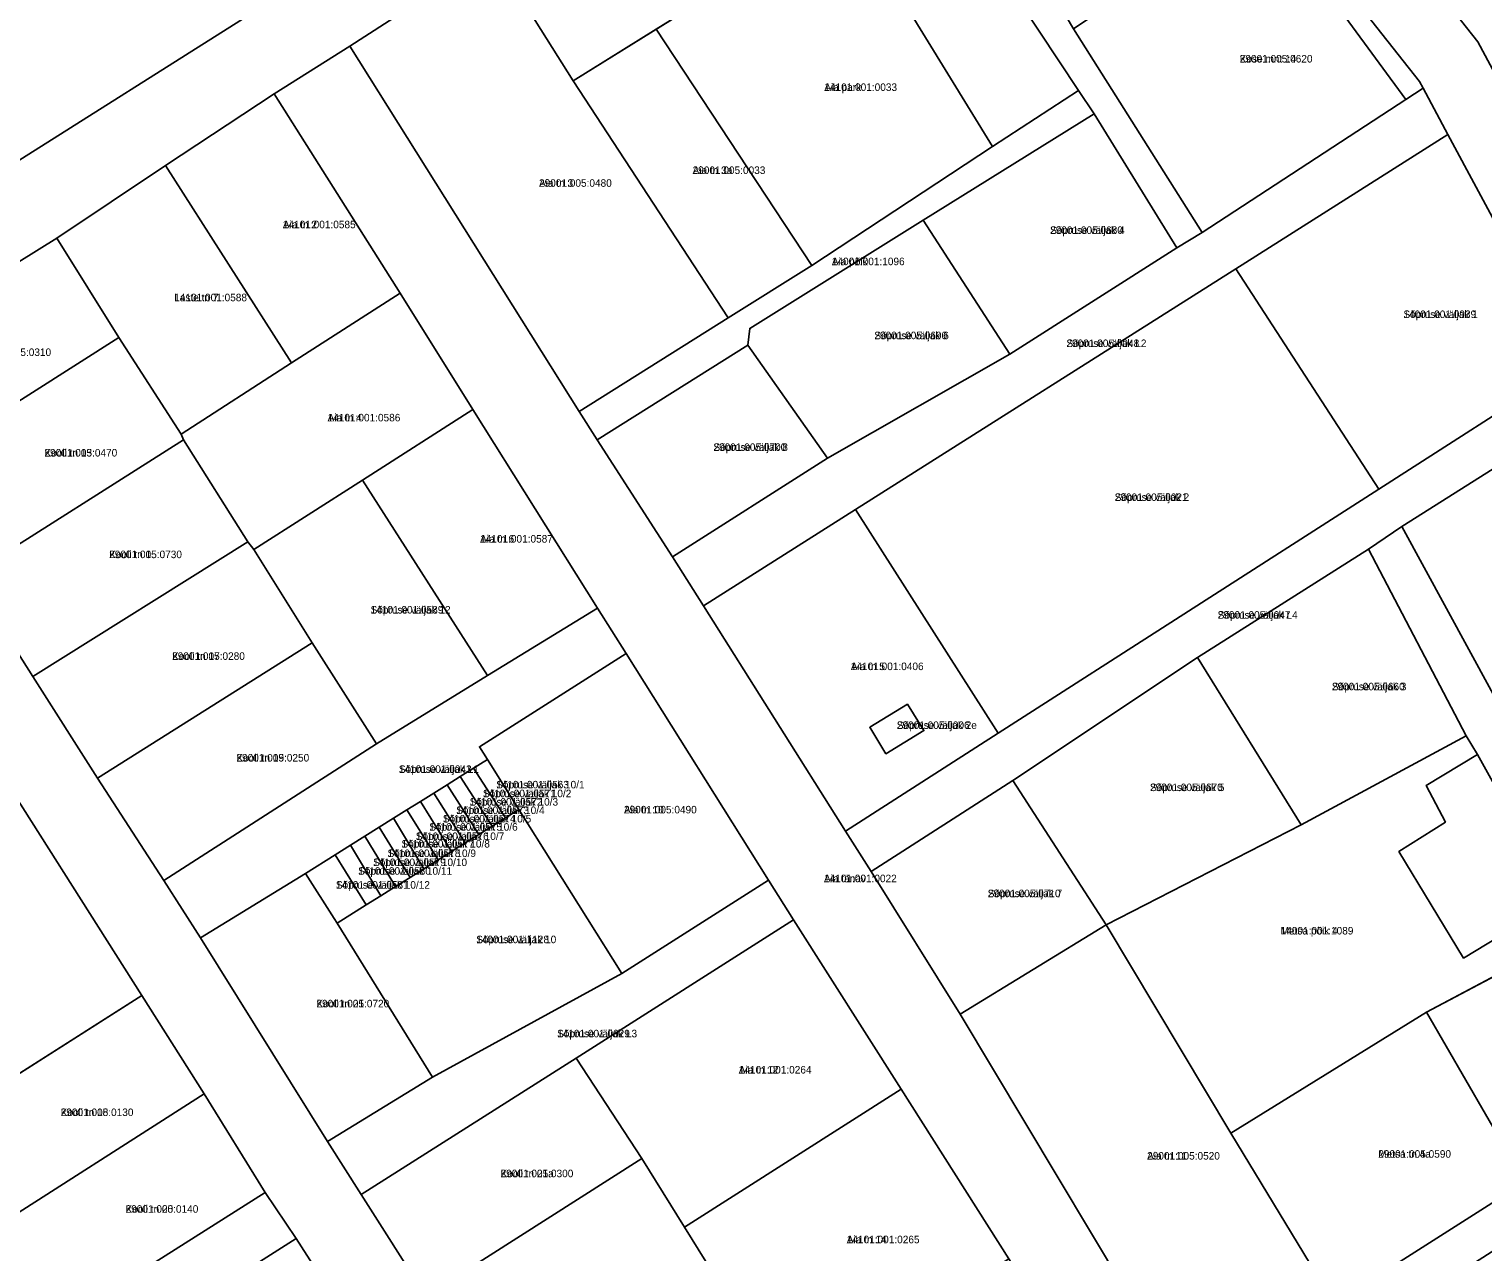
# Model space of a CAD drawing. Extents: x 566437 to 602312, y 6556921 to 6586574.
# Drawn here: x 575929.9 to 576219.6, y 6577437.6 to 6577681.1 of the extents above; entities that cross this region are included whole.
import ezdxf

# ---------------------------------------------------------------- set-up
doc = ezdxf.new("R2010")
doc.units = 0
for name, color, linetype in [('L_AADRESS', 7, 'Continuous'), ('PIIR', 7, 'Continuous'), ('TUNNUS', 7, 'Continuous')]:
    doc.layers.add(name, color=color, linetype=linetype)

msp = doc.modelspace()

# ---------------------------------------------------------------- linework, layer by layer
at = {"layer": 'PIIR'}
for points in [[(575658.06, 6577871.3), (575761.81, 6577796.47), (575774.21, 6577790.58), (575786.23, 6577773.43), (575799.52, 6577754.47), (575821.05, 6577726.98), (575839.49, 6577696.73), (575849.92, 6577679.85), (575860.57, 6577663.11), (575871.28, 6577646.07), (575883.63, 6577626.98), (575892.42, 6577612.75), (575905.11, 6577592.51), (575917.95, 6577572.24), (575930.64, 6577552.15), (575943.56, 6577531.93), (575956.74, 6577511.55), (575964.05, 6577500.13), (575989.38, 6577459.52), (575996.11, 6577448.97), (576008.97, 6577428.71)], [(575991.44, 6577860.93), (576095.59, 6577805.76), (576121.84, 6577790.98), (576139.55, 6577776.01), (576151.7, 6577763.24), (576218.61, 6577678.56), (576248.16, 6577623.5), (576275.63, 6577565.39), (576304.7, 6577497.45), (576310.07, 6577477.46), (576311.83, 6577470.8), (576312.75, 6577468.55), (576342.78, 6577388.3)], [(575996.15, 6577419.93), (575983.17, 6577440.22), (575976.96, 6577449.41), (575964.78, 6577469.07), (575952.38, 6577488.6), (575920, 6577539.6), (575917.74, 6577546.52), (575791.8, 6577745.05), (575785.06, 6577754.7), (575770.14, 6577776.75), (575727.61, 6577807.92), (575657.86, 6577856.39)], [(576320.8, 6577407.04), (576299.03, 6577465.13), (576295.24, 6577478.98), (576291.81, 6577491.53), (576291.47, 6577492.76), (576262.84, 6577559.68), (576241.04, 6577605.81), (576237.16, 6577614.03), (576235.63, 6577617.27), (576212.64, 6577660.14), (576207.7, 6577669.35), (576206.98, 6577670.69), (576141.22, 6577753.94), (576128.2, 6577767.59), (576127.04, 6577768.85), (576113.97, 6577779.34), (576111.82, 6577780.55), (576088.98, 6577793.42), (576036.81, 6577819.97), (575971.27, 6577855.43)], [(576248.16, 6577623.5), (576218.61, 6577678.56), (576151.7, 6577763.24), (576139.55, 6577776.01), (576157.74, 6577790.18), (576177.37, 6577805.48), (576182.51, 6577802.45), (576199.32, 6577795.07), (576218.92, 6577789.93), (576233.6, 6577787.54)]]:
    msp.add_lwpolyline(points, dxfattribs=at)
for points in [[(575892.66, 6577706.65), (575884.17, 6577719.47), (575919.58, 6577743.64), (575973.08, 6577774.74), (575982.13, 6577780.1), (576000.38, 6577791.22), (576049.23, 6577769.36), (576039.79, 6577762.97), (576056.89, 6577736.43), (576020.27, 6577713.34), (575926.11, 6577653.83), (575913.93, 6577673.08), (575903.24, 6577689.92)], [(575957.12, 6577653.94), (575935.45, 6577639.5), (575892.42, 6577612.75), (575883.63, 6577626.98), (575926.11, 6577653.83), (576020.27, 6577713.34), (576056.89, 6577736.43), (576074.81, 6577747.63), (576094.84, 6577760.23), (576106.96, 6577774.73), (576111.82, 6577780.55), (576113.97, 6577779.34), (576127.04, 6577768.85), (576128.2, 6577767.59), (576126.36, 6577766.11), (576099.04, 6577744.42), (576093.35, 6577740.83), (576057.79, 6577718.18), (576022.41, 6577696.17), (575993.83, 6577677.75), (575978.79, 6577668.22)], [(576207.7, 6577669.35), (576204.26, 6577667.11), (576175.5, 6577706.32), (576153.23, 6577735.81), (576126.36, 6577766.11), (576128.2, 6577767.59), (576141.22, 6577753.94), (576206.98, 6577670.69)], [(576093.35, 6577740.83), (576099.04, 6577744.42), (576118.48, 6577714.05), (576138.05, 6577681.15), (576163.66, 6577640.63), (576158.59, 6577637.57), (576142.12, 6577664.25), (576139.02, 6577668.9), (576111.36, 6577710.69), (576108.67, 6577714.61)], [(576057.79, 6577718.18), (576072.98, 6577692.38), (576038.36, 6577670.81), (576022.41, 6577696.17)], [(576121.88, 6577657.71), (576085.9, 6577634.01), (576054.86, 6577681.09), (576072.98, 6577692.38), (576108.67, 6577714.61), (576111.36, 6577710.69), (576095.69, 6577700.37)], [(576139.02, 6577668.9), (576121.88, 6577657.71), (576095.69, 6577700.37), (576111.36, 6577710.69)], [(576204.26, 6577667.11), (576163.66, 6577640.63), (576138.05, 6577681.15), (576175.5, 6577706.32)], [(576022.41, 6577696.17), (576038.36, 6577670.81), (576069.23, 6577623.6), (576039.56, 6577604.97), (575993.83, 6577677.75)], [(576038.36, 6577670.81), (576054.86, 6577681.09), (576085.9, 6577634.01), (576069.23, 6577623.6)], [(576115.45, 6577484.94), (576160.97, 6577408.98), (576166.46, 6577400.22), (576168.72, 6577396.61), (576197.83, 6577350.25), (576184.67, 6577342.16), (576172.06, 6577362.16), (576146.63, 6577402.38), (576125.16, 6577436.16), (576103.72, 6577469.96), (576082.23, 6577503.72), (576077.25, 6577511.63), (576048.87, 6577556.78), (576043.18, 6577565.81), (576018.33, 6577605.34), (576003.86, 6577628.49), (575978.79, 6577668.22), (575993.83, 6577677.75), (576039.56, 6577604.97), (576043.13, 6577599.29), (576058.11, 6577576.02), (576064.29, 6577566.24), (576092.62, 6577521.38), (576097.71, 6577513.32)], [(575982.22, 6577614.66), (575957.12, 6577653.94), (575978.79, 6577668.22), (576003.86, 6577628.49)], [(576073.17, 6577618.17), (576043.13, 6577599.29), (576039.56, 6577604.97), (576069.23, 6577623.6), (576085.9, 6577634.01), (576121.88, 6577657.71), (576139.02, 6577668.9), (576142.12, 6577664.25), (576108.09, 6577643.04), (576073.52, 6577621.5)], [(576058.11, 6577576.02), (576089.04, 6577595.66), (576125.31, 6577616.4), (576158.59, 6577637.57), (576163.66, 6577640.63), (576204.26, 6577667.11), (576207.7, 6577669.35), (576212.64, 6577660.14), (576170.37, 6577633.39), (576094.62, 6577585.44), (576064.29, 6577566.24)], [(576158.59, 6577637.57), (576125.31, 6577616.4), (576108.09, 6577643.04), (576142.12, 6577664.25)], [(576237.16, 6577614.03), (576198.88, 6577589.49), (576170.37, 6577633.39), (576212.64, 6577660.14), (576235.63, 6577617.27)], [(575947.82, 6577619.72), (575935.45, 6577639.5), (575957.12, 6577653.94), (575982.22, 6577614.66), (575960.21, 6577600.43)], [(576125.31, 6577616.4), (576089.04, 6577595.66), (576073.17, 6577618.17), (576073.52, 6577621.5), (576108.09, 6577643.04)], [(575935.45, 6577639.5), (575947.82, 6577619.72), (575905.11, 6577592.51), (575892.42, 6577612.75)], [(576094.62, 6577585.44), (576170.37, 6577633.39), (576198.88, 6577589.49), (576123.04, 6577540.88)], [(575960.7, 6577599.32), (575960.21, 6577600.43), (575982.22, 6577614.66), (576003.86, 6577628.49), (576018.33, 6577605.34), (575996.39, 6577591.3), (575974.69, 6577577.47), (575973.53, 6577579.02)], [(575917.95, 6577572.24), (575905.11, 6577592.51), (575947.82, 6577619.72), (575960.21, 6577600.43), (575960.7, 6577599.32)], [(576089.04, 6577595.66), (576058.11, 6577576.02), (576043.13, 6577599.29), (576073.17, 6577618.17)], [(576092.62, 6577521.38), (576123.04, 6577540.88), (576198.88, 6577589.49), (576237.16, 6577614.03), (576241.04, 6577605.81), (576236.78, 6577603.12), (576203.47, 6577582.07), (576196.78, 6577577.52), (576162.75, 6577555.97), (576125.94, 6577531.47), (576097.71, 6577513.32)], [(576021.26, 6577552.35), (575996.39, 6577591.3), (576018.33, 6577605.34), (576043.18, 6577565.81)], [(576258.53, 6577557.41), (576225.68, 6577541.19), (576203.47, 6577582.07), (576236.78, 6577603.12)], [(575960.7, 6577599.32), (575973.53, 6577579.02), (575930.64, 6577552.15), (575917.95, 6577572.24)], [(575986.33, 6577558.9), (575974.69, 6577577.47), (575996.39, 6577591.3), (576021.26, 6577552.35), (575999.17, 6577538.73)], [(576094.62, 6577585.44), (576123.04, 6577540.88), (576092.62, 6577521.38), (576064.29, 6577566.24)], [(576196.78, 6577577.52), (576203.47, 6577582.07), (576225.68, 6577541.19), (576241.47, 6577510.81), (576261.64, 6577473), (576256.47, 6577469.75), (576238.26, 6577501.09), (576218.5, 6577536.6), (576216.28, 6577540.36)], [(575973.53, 6577579.02), (575974.69, 6577577.47), (575986.33, 6577558.9), (575943.56, 6577531.93), (575930.64, 6577552.15)], [(576216.28, 6577540.36), (576183.39, 6577522.62), (576162.75, 6577555.97), (576196.78, 6577577.52)], [(576021.26, 6577535.63), (576018.47, 6577533.88), (576015.85, 6577532.24), (576013.2, 6577530.59), (576010.54, 6577528.93), (576007.9, 6577527.27), (576005.21, 6577525.59), (576002.54, 6577523.92), (575999.68, 6577522.13), (575996.85, 6577520.36), (575993.95, 6577518.55), (575990.92, 6577516.65), (575985, 6577512.95), (575964.05, 6577500.13), (575956.74, 6577511.55), (575999.17, 6577538.73), (576021.26, 6577552.35), (576043.18, 6577565.81), (576048.87, 6577556.78), (576019.67, 6577538.17)], [(575986.33, 6577558.9), (575999.17, 6577538.73), (575956.74, 6577511.55), (575943.56, 6577531.93)], [(576077.25, 6577511.63), (576048.06, 6577493.02), (576027.51, 6577525.69), (576021.26, 6577535.63), (576019.67, 6577538.17), (576048.87, 6577556.78)], [(576183.39, 6577522.62), (576144.55, 6577502.72), (576125.94, 6577531.47), (576162.75, 6577555.97)], [(576104.92, 6577546.65), (576108.21, 6577541.41), (576100.66, 6577536.79), (576097.43, 6577542.07)], [(576097.43, 6577542.07), (576100.66, 6577536.79), (576108.21, 6577541.41), (576104.92, 6577546.65)], [(575851.95, 6577497.56), (575920, 6577539.6), (575952.38, 6577488.6), (575916.78, 6577465.99), (575904.32, 6577486.07), (575870.5, 6577465.08)], [(576208.36, 6577485.34), (576169.39, 6577461.19), (576144.55, 6577502.72), (576183.39, 6577522.62), (576216.28, 6577540.36), (576218.5, 6577536.6), (576208.28, 6577530.44), (576212.12, 6577523.18), (576202.87, 6577517.29), (576215.74, 6577496.07), (576225.14, 6577501.77), (576228.78, 6577496.1)], [(576018.47, 6577533.88), (576021.26, 6577535.63), (576027.51, 6577525.69), (576024.84, 6577524.02)], [(576218.5, 6577536.6), (576238.26, 6577501.09), (576228.78, 6577496.1), (576225.14, 6577501.77), (576215.74, 6577496.07), (576202.87, 6577517.29), (576212.12, 6577523.18), (576208.28, 6577530.44)], [(576013.2, 6577530.59), (576015.85, 6577532.24), (576022.21, 6577522.38), (576019.52, 6577520.69)], [(576015.85, 6577532.24), (576018.47, 6577533.88), (576024.84, 6577524.02), (576022.21, 6577522.38)], [(576010.54, 6577528.93), (576013.2, 6577530.59), (576019.52, 6577520.69), (576016.82, 6577519.01)], [(576144.55, 6577502.72), (576115.45, 6577484.94), (576097.71, 6577513.32), (576125.94, 6577531.47)], [(576005.21, 6577525.59), (576007.9, 6577527.27), (576014.12, 6577517.31), (576011.44, 6577515.64)], [(576007.9, 6577527.27), (576010.54, 6577528.93), (576016.82, 6577519.01), (576014.12, 6577517.31)], [(576000.03, 6577508.5), (576002.96, 6577510.33), (576005.84, 6577512.14), (576008.56, 6577513.83), (576011.44, 6577515.64), (576014.12, 6577517.31), (576016.82, 6577519.01), (576019.52, 6577520.69), (576022.21, 6577522.38), (576024.84, 6577524.02), (576027.51, 6577525.69), (576048.06, 6577493.02), (576010.32, 6577472.38), (575991.28, 6577503.03), (575997.12, 6577506.68)], [(575999.68, 6577522.13), (576002.54, 6577523.92), (576008.56, 6577513.83), (576005.84, 6577512.14)], [(576002.54, 6577523.92), (576005.21, 6577525.59), (576011.44, 6577515.64), (576008.56, 6577513.83)], [(575996.85, 6577520.36), (575999.68, 6577522.13), (576005.84, 6577512.14), (576002.96, 6577510.33)], [(575990.92, 6577516.65), (575993.95, 6577518.55), (576000.03, 6577508.5), (575997.12, 6577506.68)], [(575993.95, 6577518.55), (575996.85, 6577520.36), (576002.96, 6577510.33), (576000.03, 6577508.5)], [(575985, 6577512.95), (575990.92, 6577516.65), (575997.12, 6577506.68), (575991.28, 6577503.03), (575990.72, 6577503.94)], [(575985, 6577512.95), (575990.72, 6577503.94), (575991.28, 6577503.03), (576010.32, 6577472.38), (575989.38, 6577459.52), (575964.05, 6577500.13)], [(576038.93, 6577476.14), (575996.11, 6577448.97), (575989.38, 6577459.52), (576010.32, 6577472.38), (576048.06, 6577493.02), (576077.25, 6577511.63), (576082.23, 6577503.72)], [(576052.02, 6577456.14), (576038.93, 6577476.14), (576082.23, 6577503.72), (576103.72, 6577469.96), (576060.54, 6577442.46)], [(576169.39, 6577461.19), (576189.95, 6577427.3), (576160.97, 6577408.98), (576115.45, 6577484.94), (576144.55, 6577502.72)], [(576256.47, 6577469.75), (576227.99, 6577451.43), (576208.36, 6577485.34), (576238.26, 6577501.09)], [(576160.97, 6577408.98), (576189.95, 6577427.3), (576227.99, 6577451.43), (576256.47, 6577469.75), (576261.64, 6577473), (576287.4, 6577488.84), (576291.81, 6577491.53), (576295.24, 6577478.98), (576263.92, 6577462.16), (576237.52, 6577447.91), (576217.92, 6577435.36), (576205.27, 6577426.72), (576166.46, 6577400.22)], [(575964.78, 6577469.07), (575920.34, 6577440.63), (575907.36, 6577460.01), (575952.38, 6577488.6)], [(576227.99, 6577451.43), (576189.95, 6577427.3), (576169.39, 6577461.19), (576208.36, 6577485.34)], [(576052.02, 6577456.14), (576008.97, 6577428.71), (575996.11, 6577448.97), (576038.93, 6577476.14)], [(575920.34, 6577440.63), (575964.78, 6577469.07), (575976.96, 6577449.41), (575933.16, 6577421.65), (575928.94, 6577427.9)], [(576064.77, 6577435.63), (576060.54, 6577442.46), (576103.72, 6577469.96), (576125.16, 6577436.16), (576082.05, 6577408.59), (576077.71, 6577415.46)], [(576008.97, 6577428.71), (576052.02, 6577456.14), (576060.54, 6577442.46), (576064.77, 6577435.63), (576021.84, 6577408.44)], [(575983.17, 6577440.22), (575939.12, 6577412.24), (575933.82, 6577420.67), (575933.16, 6577421.65), (575976.96, 6577449.41)], [(575996.15, 6577419.93), (575951.98, 6577392.21), (575939.12, 6577412.24), (575983.17, 6577440.22)]]:
    msp.add_lwpolyline(points, close=True, dxfattribs=at)

# ---------------------------------------------------------------- texts
at = {"layer": 'L_AADRESS'}
for s, p in [('Kose mnt 14', (576171.15, 6577674.46)), ('Aia park', (576088.37, 6577668.8)), ('Aia tn 3a', (576062.13, 6577652.26)), ('Aia tn 3', (576031.53, 6577649.71)), ('Aia tn 2', (575980.49, 6577641.45)), ('Sõpruse väljak 4', (576133.37, 6577640.32)), ('Aia põik', (576089.88, 6577634.09)), ('Laste tn 7', (575958.84, 6577626.91)), ('Sõpruse väljak 1', (576203.76, 6577623.57)), ('Sõpruse väljak 6', (576098.35, 6577619.35)), ('Sõpruse väljak L2', (576136.62, 6577617.79)), ('Aia tn 4', (575989.4, 6577602.98)), ('Sõpruse väljak 8', (576066.29, 6577597.1)), ('Kooli tn 13', (575932.99, 6577595.98)), ('Sõpruse väljak 2', (576146.25, 6577587.13)), ('Aia tn 6', (576019.79, 6577578.84)), ('Kooli tn 15', (575945.88, 6577575.74)), ('Sõpruse väljak 12', (575997.97, 6577564.71)), ('Sõpruse väljak L4', (576166.76, 6577563.68)), ('Kooli tn 17', (575958.42, 6577555.48)), ('Aia tn 5', (576093.66, 6577553.44)), ('Sõpruse väljak 3', (576189.52, 6577549.42)), ('Sõpruse väljak 2e', (576102.83, 6577541.72)), ('Kooli tn 19', (575971.24, 6577535.23)), ('Sõpruse väljak L1', (576003.6, 6577532.97)), ('Sõpruse väljak 10/2', (576020.35, 6577528.12)), ('Sõpruse väljak 10/1', (576022.99, 6577529.88)), ('Sõpruse väljak 5', (576153.27, 6577529.34)), ('Sõpruse väljak 10/4', (576015.03, 6577524.78)), ('Sõpruse väljak 10/3', (576017.71, 6577526.45)), ('Aia tn 10', (576048.46, 6577524.9)), ('Sõpruse väljak 10/5', (576012.36, 6577523.09)), ('Sõpruse väljak 10/7', (576006.99, 6577519.6)), ('Sõpruse väljak 10/6', (576009.66, 6577521.46)), ('Sõpruse väljak 10/9', (576001.35, 6577516.21)), ('Sõpruse väljak 10/8', (576004.12, 6577518.1)), ('Sõpruse väljak 10/10', (575998.46, 6577514.41)), ('Sõpruse väljak 10/11', (575995.48, 6577512.68)), ('Aia tänav', (576088.31, 6577511.19)), ('Sõpruse väljak 10/12', (575991.06, 6577509.91)), ('Sõpruse väljak 7', (576120.95, 6577508.21)), ('Sõpruse väljak 10', (576019.02, 6577499.04)), ('Metsa põik 4', (576179.3, 6577500.78)), ('Kooli tn 21', (575987.18, 6577486.27)), ('Sõpruse väljak L3', (576035.13, 6577480.3)), ('Aia tn 12', (576071.33, 6577473.09)), ('Kooli tn 18', (575936.22, 6577464.62)), ('Aia tn 11', (576152.7, 6577455.94)), ('Metsa tn 4a', (576198.75, 6577456.32)), ('Kooli tn 21a', (576023.87, 6577452.43)), ('Kooli tn 20', (575949.15, 6577445.36)), ('Aia tn 14', (576092.85, 6577439.28))]:
    msp.add_text(s, height=1.5, dxfattribs=at).set_placement(p)
at = {"layer": 'TUNNUS'}
for s, p in [('29001:005:0620', (576171.15, 6577674.46)), ('14101:001:0033', (576088.37, 6577668.8)), ('29001:005:0033', (576062.13, 6577652.26)), ('29001:005:0480', (576031.53, 6577649.71)), ('14101:001:0585', (575980.49, 6577641.45)), ('29001:005:0680', (576133.37, 6577640.32)), ('14001:001:1096', (576089.88, 6577634.09)), ('14101:001:0588', (575958.84, 6577626.91)), ('14001:001:0939', (576203.76, 6577623.57)), ('29001:005:0690', (576098.35, 6577619.35)), ('29001:005:0048', (576136.62, 6577617.79)), ('29001:005:0310', (575919.82, 6577616.01)), ('14101:001:0586', (575989.4, 6577602.98)), ('29001:005:0700', (576066.29, 6577597.1)), ('29001:005:0470', (575932.99, 6577595.98)), ('29001:005:0021', (576146.25, 6577587.13)), ('14101:001:0587', (576019.79, 6577578.84)), ('29001:005:0730', (575945.88, 6577575.74)), ('14101:001:0589', (575997.97, 6577564.71)), ('29001:005:0047', (576166.76, 6577563.68)), ('29001:005:0280', (575958.42, 6577555.48)), ('14101:001:0406', (576093.66, 6577553.44)), ('29001:005:0660', (576189.52, 6577549.42)), ('29001:005:0006', (576102.83, 6577541.72)), ('29001:005:0250', (575971.24, 6577535.23)), ('14101:001:0043', (576003.6, 6577532.97)), ('14101:001:0571', (576020.35, 6577528.12)), ('14101:001:0563', (576022.99, 6577529.88)), ('29001:005:0670', (576153.27, 6577529.34)), ('14101:001:0573', (576015.03, 6577524.78)), ('14101:001:0572', (576017.71, 6577526.45)), ('29001:005:0490', (576048.46, 6577524.9)), ('14101:001:0574', (576012.36, 6577523.09)), ('14101:001:0576', (576006.99, 6577519.6)), ('14101:001:0575', (576009.66, 6577521.46)), ('14101:001:0578', (576001.35, 6577516.21)), ('14101:001:0577', (576004.12, 6577518.1)), ('14101:001:0579', (575998.46, 6577514.41)), ('14101:001:0580', (575995.48, 6577512.68)), ('14101:001:0022', (576088.31, 6577511.19)), ('14101:001:0581', (575991.06, 6577509.91)), ('29001:005:0710', (576120.95, 6577508.21)), ('14001:001:1128', (576019.02, 6577499.04)), ('14001:001:1089', (576179.3, 6577500.78)), ('29001:005:0720', (575987.18, 6577486.27)), ('14101:001:0029', (576035.13, 6577480.3)), ('14101:001:0264', (576071.33, 6577473.09)), ('29001:005:0130', (575936.22, 6577464.62)), ('29001:005:0520', (576152.7, 6577455.94)), ('29001:005:0590', (576198.75, 6577456.32)), ('29001:005:0300', (576023.87, 6577452.43)), ('29001:005:0140', (575949.15, 6577445.36)), ('14101:001:0265', (576092.85, 6577439.28))]:
    msp.add_text(s, height=1.5, dxfattribs=at).set_placement(p)

doc.saveas('drawing.dxf')
